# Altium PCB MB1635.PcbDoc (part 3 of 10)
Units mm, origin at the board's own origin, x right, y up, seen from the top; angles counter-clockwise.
Board outline 127 x 97 mm, 6 copper layers (Top Layer, Signal Layer 1, Signal Layer 2, Signal Layer 3, Signal Layer 4, Bottom Layer), stack 1.557 mm thick; 593 components, 478 nets, 2435 pads, 1743 vias.
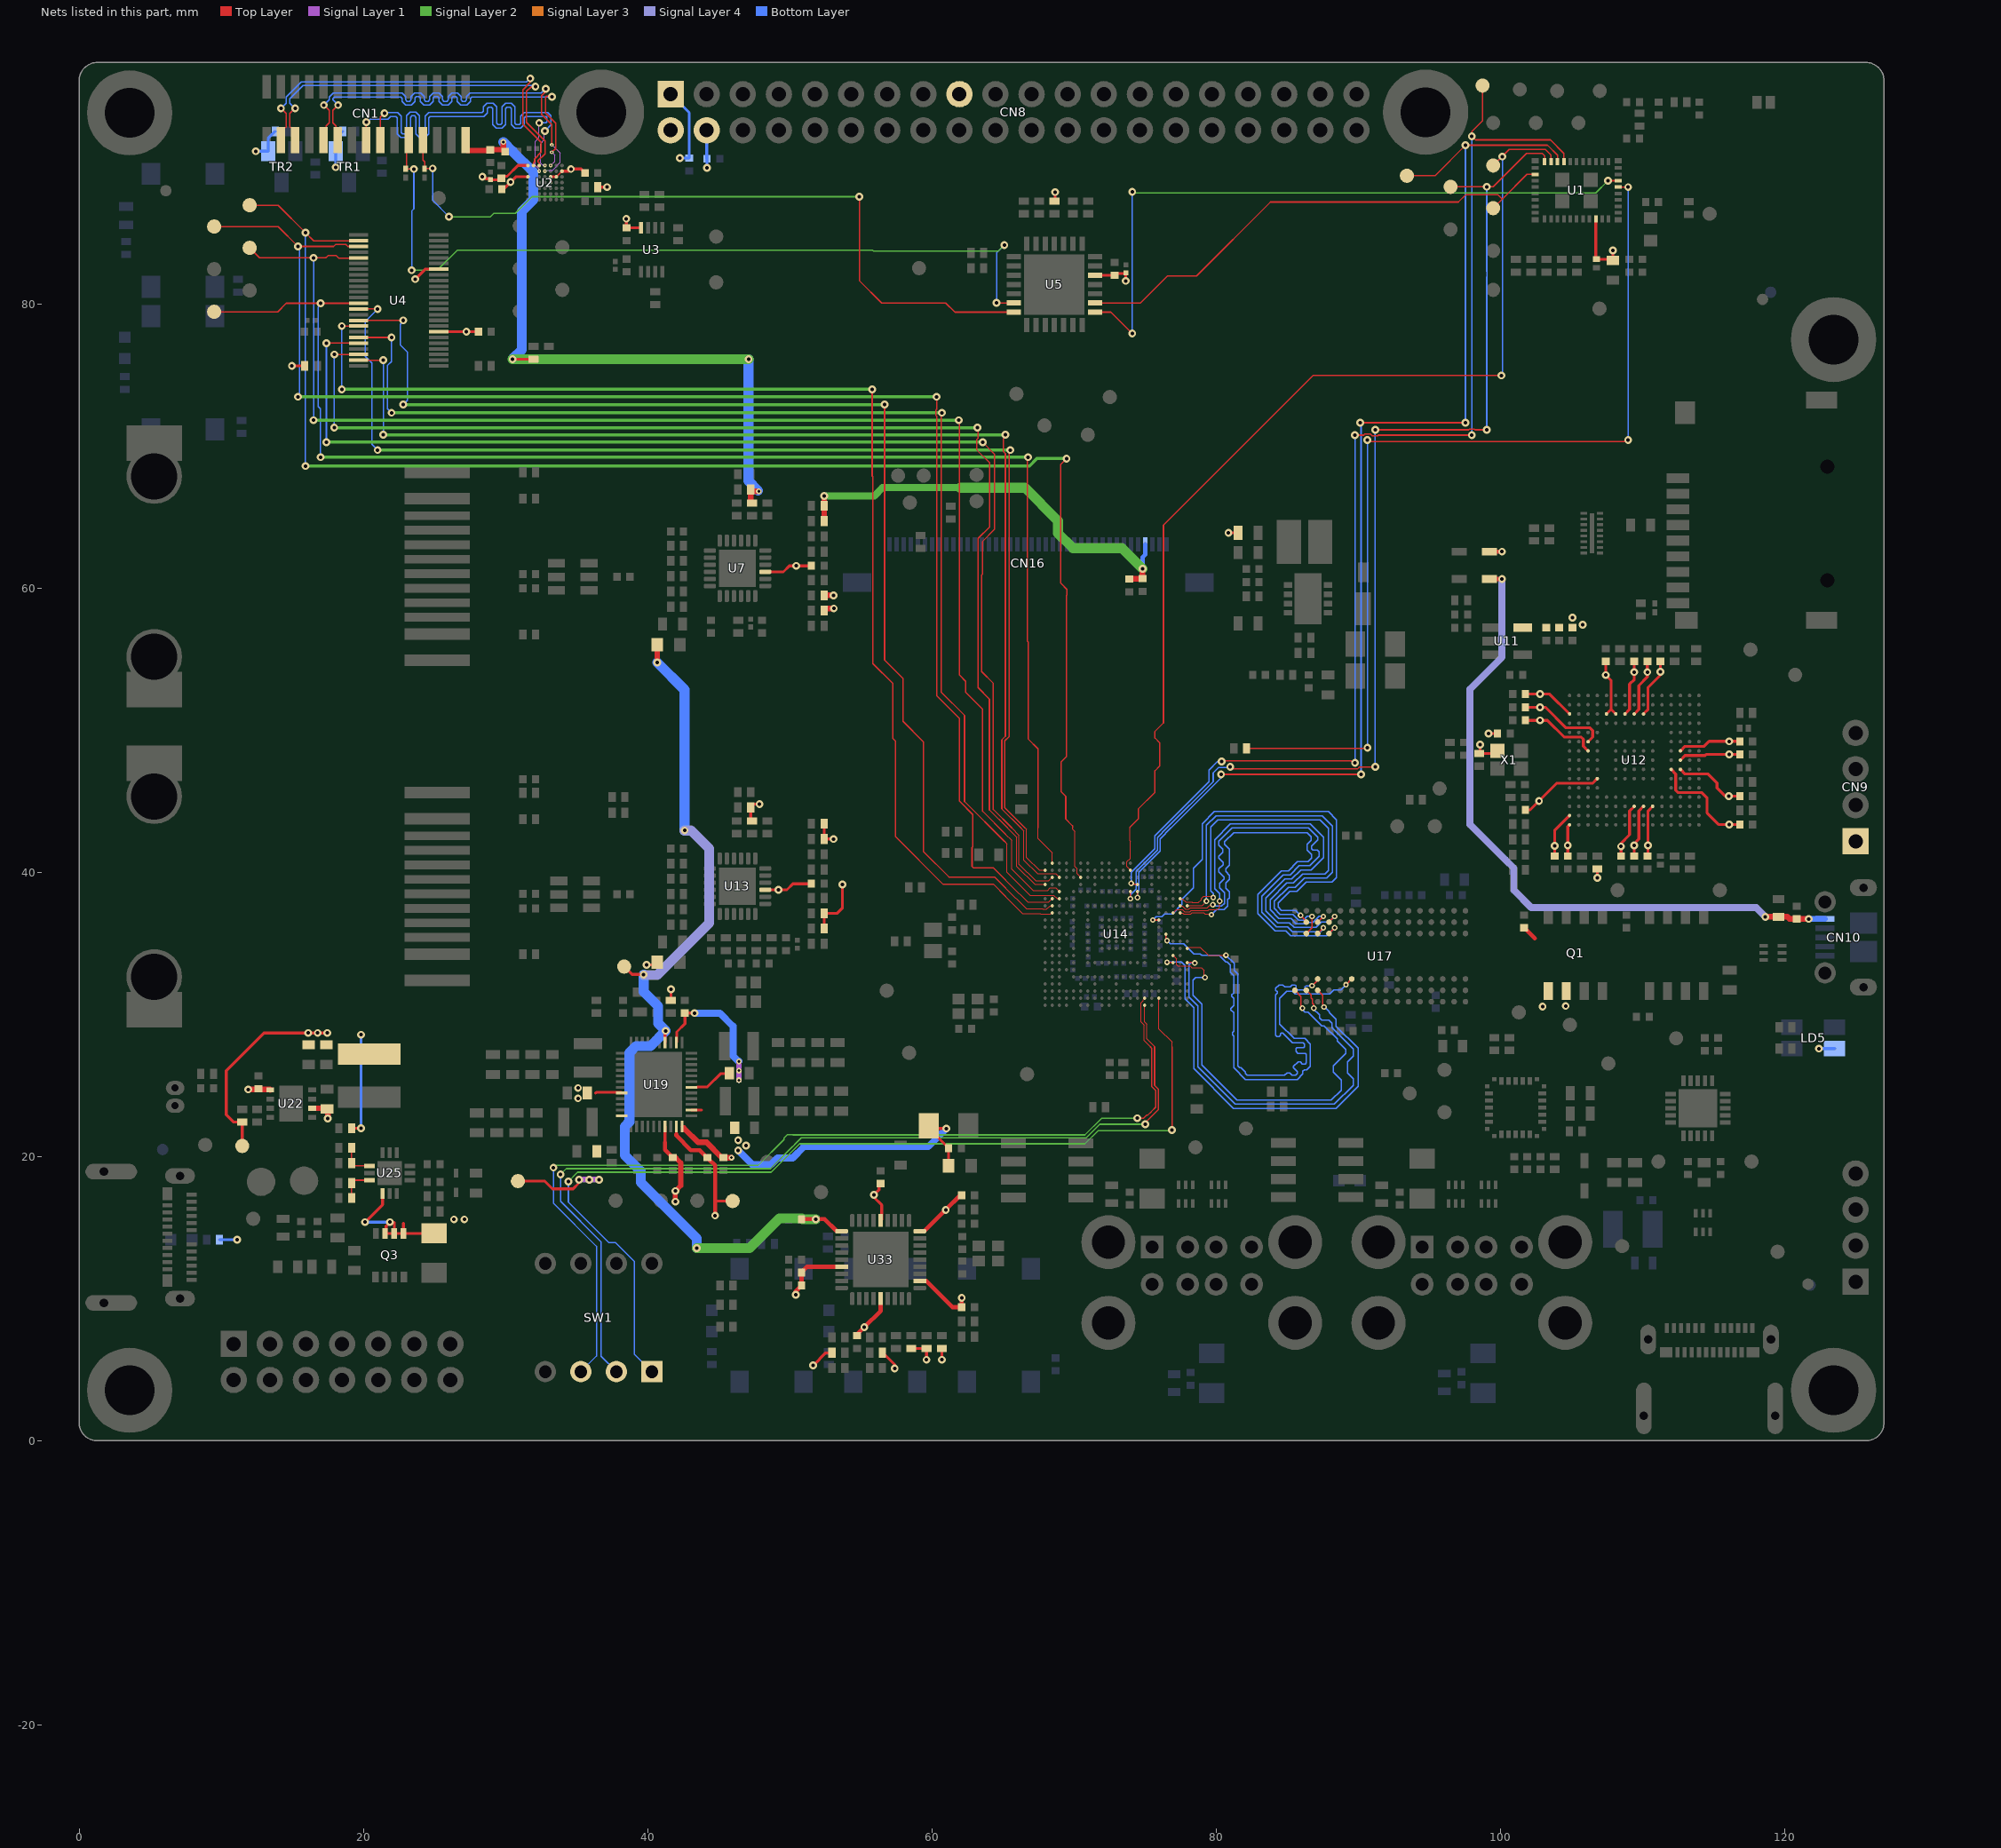
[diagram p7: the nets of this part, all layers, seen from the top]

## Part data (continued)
R31 R71 R75 R80 R82 R108 R120 R121 R168 R169: library part MCD-00068, "Resistor, 1K5, 0402, +/-1%, 1/16W", Manufacturer=YAGEO, Manufacturer_Part_Number=RC0402FR-071K5L, Package=0402
R35 R123 R127 R131 R138 R151: library part MCD-00181, "Resistor, 0R, 0603, +/- 0.5mR, 1/4W", Manufacturer=ROHM, Manufacturer_Part_Number=PMR03EZPJ000, Package=0603
R36 R41 R51 R79 R86 R98 R109: library part MCD-00455, "Resistor, 33R, 0402, +/-1%, 1/16W", Manufacturer=YAGEO, Manufacturer_Part_Number=RC0402FR-0733RL, Package=0402
R37 R39 R40 R42 R92 R95 R97 R99: library part MCD-00565, "Resistor, 49R9, 0402, +/-1%, 1/16W", Manufacturer=YAGEO, Manufacturer_Part_Number=RC0402FR-0749R9L, Package=0402
R44 R46 R156 R158 R159 R160 R161 R164 R165: library part MCD-00059, "Resistor, 100K, 0402, +/-1%, 1/16W", Manufacturer=YAGEO, Manufacturer_Part_Number=RC0402FR-07100KL, Package=0402
R47 R101: library part MCD-00723, "Resistor, 12K1, 0402, +/-1%, 1/16W", Manufacturer=YAGEO, Manufacturer_Part_Number=RC0402FR-0712K1L, Package=0402
R49: library part MCD-00060, "Resistor, 10R, 0603, +/-1%, 1/4W", Manufacturer=ROHM, Manufacturer_Part_Number=ESR03EZPF10R0, Package=0603
R50 R107: library part MCD-00189, "Resistor, 22R, 0402, +/-1%, 1/16W", Manufacturer=YAGEO, Manufacturer_Part_Number=RC0402FR-0722RL, Package=0402
R62 R63 R148: library part MCD-00433, "Resistor, 2K4, 0402, +/-1%, 1/16W", Manufacturer=YAGEO, Manufacturer_Part_Number=RC0402FR-072K4L, Package=0402
R66 R128: library part MCD-00185, "Resistor, 3K, 0402, +/-1%, 1/16W", Manufacturer=YAGEO, Manufacturer_Part_Number=RC0402FR-073KL, Package=0402
R74 R173 R175 R177 R182: library part MCD-00067, "Resistor, 100R, 0402, +/- 1%, 1/16W", Manufacturer=YAGEO, Manufacturer_Part_Number=RC0402FR-07100RL, Package=0402
R111: library part MCD-03129, "Resistor, 12mR, 0603, 1%, 1/2W", Manufacturer=PANASONIC, Manufacturer_Part_Number=ERJ-3BWFR022V, Package=0603
R112 R179: library part MCD-00120, "Resistor, 240R, 0402, +/-1%, 1/16W", Manufacturer=YAGEO, Manufacturer_Part_Number=RC0402FR-07240RL, Package=0402
R113 R124 R137: library part MCD-02234, "Resistor, 100mR, 0603, +/- 1%, 1/3W", Manufacturer=PANASONIC, Manufacturer_Part_Number=ERJ-3BWFR100V, Package=0603
R117 R125 R152 R183: library part MCD-00062, "Resistor, 330R, 0402, +/-1%, 1/16W", Manufacturer=YAGEO, Manufacturer_Part_Number=RC0402FR-07330RL, Package=0402
R126 R132: library part MCD-02233, "Resistor, 50mR, 0603, +/-1%, 1/3W", Manufacturer=PANASONIC, Manufacturer_Part_Number=ERJ-3BWFR050V, Package=0603
R129: library part MCD-00384, "Resistor, 13K, 0603,+/-1%, 1/10W", Manufacturer=YAGEO, Manufacturer_Part_Number=RC0603FR-0713KL, Package=0603
R134: library part MCD-00420, "Resistor, 2K ,0603, +/-1%, 1/10W", Manufacturer=YAGEO, Manufacturer_Part_Number=RC0603FR-072KL, Package=0603
R135: library part MCD-00521, "Resistor, 75K, 0402, +/-1%, 1/16W", Manufacturer=YAGEO, Manufacturer_Part_Number=RC0402FR-0775KL, Package=0402
R136: library part MCD-00435, "Resistor, 24K, 0402, +/-1%, 1/16W", Manufacturer=YAGEO, Manufacturer_Part_Number=RC0402FR-0724KL, Package=0402
R142: library part MCD-00259, "Resistor, 33K, 0603, +/-1%, 1/10W", Manufacturer=YAGEO, Manufacturer_Part_Number=RC0603FR-0733KL, Package=0603
R143: library part MCD-00530, "Resistor, 8K2, 0603, +/-1%, 1/10W", Manufacturer=YAGEO, Manufacturer_Part_Number=RC0603FR-078K2L, Package=0603
R145 R147: library part MCD-00333, "Resistor, 5K1, 0402, +/-1%, 1/16W", Manufacturer=YAGEO, Manufacturer_Part_Number=RC0402FR-075K1L, Package=0402
R146: library part MCD-00187, "Resistor, 12K, 0402, +/-1%, 1/16W", Manufacturer=YAGEO, Manufacturer_Part_Number=RC0402FR-0712KL, Package=0402
R153 R154 R155 R157 R170 R171 R174 R181: library part MCD-00061, "Resistor, 1K, 0402, +/-1%,1/16W", Manufacturer=YAGEO, Manufacturer_Part_Number=RC0402FR-071KL, Package=0402
R172 R184: library part MCD-00507, "Resistor, 680R, 0402, +/-1%, 1/16W", Manufacturer=YAGEO, Manufacturer_Part_Number=RC0402FR-07680RL, Package=0402
R185: library part MCD-01512, "Resistor, 1R, 0603, +/-1%, 1/10W", Manufacturer=YAGEO, Manufacturer_Part_Number=RC0603FR-071RL, Package=0603
R186: library part MCD-00489, "Resistor, 560R, 0402, +/-1%, 1/16W", Manufacturer=YAGEO, Manufacturer_Part_Number=RC0402FR-07560RL, Package=0402
SW1: library part MCD-02256, "Quad SPST switch, TH, 2.54mm pitch, height 7.5mm", Manufacturer=GRAYHILL, Package="DIP8 2.54mm pitch"
TP1 TP2 TP3 TP4 TP5 TP6 TP7 TP8 TP9 TP10 TP11 TP12 TP13 TP14 TP15 TP16 TP17 TP18 TP19 TP20 TP21 TP22 TP23 TP24 TP25 TP26 TP27 TP28 TP29 TP30 TP31 TP32 TP33 TP34 TP35 TP36 TP37 TP38 TP39 TP40 TP41 TP42 TP43 TP44 TP45 TP46 TP47 TP48 TP49 TP50 TP51 TP52 TP53 TP54 TP55 TP56 TP57 TP58 TP59 TP61 TP62 TP63 TP64 TP65 TP66 TP67 TP69 TP70 TP71 TP72 TP73 TP74 TP75 TP77: library part MCD-00074, "Test Point 1mm", Manufacturer=N/A
TP68 TP76: library part MCD-00177, "Test Point 2mm", Manufacturer=N/A
TR1 TR2: library part MCD-02156, "MOSFET, N-Channel , Vds: 25V, Id: 0,22A, Vgs(th): 1.06V, Vgs(max): +/-8V, Rdson:5ohm@Vgs=2.7V, Qg=0,49nC", Manufacturer="ON SEMICONDUCTOR", Manufacturer_Part_Number=FDV301N, Package=SOT23-3
U1: library part MCD-00268, "IEEE802.11b/g/n W-LAN + Bluetooth 4.1+EDR module", Manufacturer=MURATA, Manufacturer_Part_Number=LBEE5KL1DX-977
U2: library part MCD-02213, "Dual mode MIPI CSI-2 / SMIA CCP2 de-serializer", Manufacturer=STMICROELECTRONICS, Manufacturer_HQ_COO=EU, Manufacturer_Part_Number=STMIPID02/TR, Package="VFBGA 49-ball, 3x3x1mm, 0.4mm pitch"
U3: library part MCD-00264, "Dual bit dual supply bus transceiver", Manufacturer="TEXAS INSTRUMENTS"
U4: library part MCD-02226, "16-bit translating transceiver", Manufacturer="TEXAS INSTRUMENTS", Manufacturer_Part_Number=SN74AVC16T245DGVR, Package="TVSOP,  56-ball 4.5x7mm, 0.65mm pitch"
U5: library part MCD-02210, "16-bit port expander with I2C control", Manufacturer=MICROCHIP, Manufacturer_Part_Number=MCP23017T-E/ML, Package="QFN28 6x6mm"
U6: library part MCD-00249, "ESD protection for SD card 2.0", Manufacturer=STMICROELECTRONICS, Manufacturer_HQ_COO=EU
U7 U13: library part MCD-00719, "10/100M RMII Ethernet transceiver", Manufacturer=MICROCHIP
U8 U15: library part MCD-00250, "Very low capacitance ESD protection , 4 lines", Manufacturer=STMICROELECTRONICS, Manufacturer_HQ_COO=EU
U9: library part MCD-00082, "White LED power supply for large display backlight, QFN8", Manufacturer=STMICROELECTRONICS, Manufacturer_HQ_COO=EU
U10 U37 U40 U41: library part MCD-00170, "ESD protection 6V1", Manufacturer=STMICROELECTRONICS, Manufacturer_HQ_COO=EU, Manufacturer_Part_Number=ESDALC6V1-1U2
U11: library part MCD-00086, "Ultra low drop-low noise BiCMOS voltage, regulators low ESR capacitors compatible", Manufacturer=STMICROELECTRONICS, Manufacturer_HQ_COO=EU
U12: library part MCD-01523, "MCU, Arm Cortex-M7 32-bit MCU, 512KB Flash, 276KB RAM, With Crypto", Manufacturer=STMICROELECTRONICS, Manufacturer_HQ_COO=EU, Manufacturer_Part_Number=STM32F723IEK6, Package=ICC_UFBGA201_176+25_10X10_P065
U14: library part MCD-02251, "Cortex-A7 @ 900MHz, 128KB-ROM, 128KB-SRAM, 2x Ethernet, 2x ADC, 2x CAN FD, TSC, Camera, Display, Secure Boot, Cryptography, DRAM enc/dec, PKA", Manufacturer=STMICROELECTRONICS, Manufacturer_HQ_COO=EU, Package=TFBGA320
U16: library part MCD-00251, "High power transient voltage suppressor, 7V breakdown", Manufacturer=STMICROELECTRONICS, Manufacturer_HQ_COO=EU, Manufacturer_Part_Number=ESDA7P60-1U1M
U17: library part MCD-01811, "Memory,DDR3L,4Gb,256Mbx16,933Mhz,1V35,TFBGA", Manufacturer=NANYA
U18 U26 U27 U28 U29 U32: library part MCD-00649, "Common mode filter with ESD protection for USB 2.0 interface", Manufacturer=STMICROELECTRONICS, Manufacturer_HQ_COO=EU
U19: library part MCD-02275, "ST PMIC: 4 step-down +1 advanced boost SMPS, 6 LDOs, 2 pwr switches, DDR Vref, NVM option 'D' for IO@3.3V", Manufacturer=STMICROELECTRONICS, Manufacturer_Part_Number=STPMIC1DPQR, Package="WFQFN 5.0x6.0x0.80mm"
U20: library part MCD-02130, "USB Type-C Port Protection for USB DRP Power Delivery, PPS compliant", Manufacturer=STMICROELECTRONICS, Manufacturer_HQ_COO=EU, Package=QFN-20L
U21: library part MCD-02218, "Arm Cortex-M0+ 32-bit MCU, up to 128 KB Flash, 36 KB RAM,  4x USART, timers, ADC, DAC, comm. I/Fs, 1.7-3.6V", Manufacturer=STMICROELECTRONICS, Manufacturer_HQ_COO=EU, Package=UFQFPN28
U22: library part MCD-02243, "3A DC step-down switching regulator 1,5MHz", Manufacturer=STMICROELECTRONICS, Manufacturer_HQ_COO=EU, Package="VFDFPN 3x3mm - 8L"
U23 U24: library part MCD-00123, "IC,Dual-Channel-Power-Switch,500mA,100mR,SO8", Manufacturer=STMICROELECTRONICS, Manufacturer_HQ_COO=EU
U25: library part MCD-01809, "USB Type-C Port Protection for USB Power Delivery, PPS compliant", Manufacturer=STMICROELECTRONICS, Manufacturer_HQ_COO=EU, Package=QFN-12L
U30 U31 U38 U39: library part MCD-01026, "High power transient voltage suppressor", Manufacturer=STMICROELECTRONICS, Manufacturer_HQ_COO=EU, Manufacturer_Part_Number=ESDA7P120-1U1M, Package=QFN1610
U33: library part MCD-00145, "USB HUB 2,0 Controller", Manufacturer=MICROCHIP
U34 U36: library part MCD-01207, "High power Transient voltage suppressor:25V/35A EOS and ESD transients protection.", Manufacturer=STMICROELECTRONICS, Manufacturer_HQ_COO=EU, Manufacturer_Part_Number=ESDA25P35-1U1M, Package=QFN1610
U35: library part MCD-02422, "LCD,  TFT, 4.3 inch, 480x272 pixels with LED Backlight and Capacitive touch panel, high luminance with 0.5mm pitch flat cable", Manufacturer=ROCKTECH, Manufacturer_Part_Number=RK043FN78HV-CT661C
X1: library part MCD-00597, "Oscillator, SPXO, 25Mhz, +/-50ppm, 3V3, square wave, 2.5x2mm", Manufacturer=NDK, Manufacturer_Part_Number=NZ2520SH-25MHZ-END4869C, Package=2.5x2mm
X2: library part MCD-01479, "Crystal, 32.768kHz, 6pF, +/-20ppm, 80K, 2.05x1.2mm", Manufacturer=NDK, Manufacturer_Part_Number=NX2012SA-32.768KHZ-EXS00A-MU00527, Package=2.05x1.2mm
X3: library part MCD-01364, "Crystal, 25MHz, 6pF, +/-20ppm, 80R, 2x1.6mm", Manufacturer=NDK, Manufacturer_Part_Number=NX2016SA-25MHZ-EXS00A-CS11321, Package=2x1.6mm
X4 X5: library part MCD-01036, "Crystal, 24MHz, 6pF, +/-20ppm, 80R, 2x1.6mm", Manufacturer=NDK, Manufacturer_Part_Number=NX2016SA-24MHZ-EXS00A-CS10820, Package=2x1.6mm

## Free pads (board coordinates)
  round 6 hole 3.5: 1(3.55,3.55) 1(3.55,93.45) 1(36.75,93.5) 1(94.75,93.5) 1(123.45,3.55) 1(123.45,77.5)

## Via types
v1: diameter 0.55, hole 0.25, Top Layer to Bottom Layer, 1438 vias
v2: diameter 0.4, hole 0.2, Top Layer to Bottom Layer, 276 vias
v3: diameter 0.26, hole 0.1, Top Layer to Signal Layer 1, tented both sides, 29 vias

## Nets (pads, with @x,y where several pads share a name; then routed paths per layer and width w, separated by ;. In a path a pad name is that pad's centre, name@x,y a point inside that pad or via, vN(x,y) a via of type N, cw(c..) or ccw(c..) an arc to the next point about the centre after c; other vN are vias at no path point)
1V8_PERIPH: C9.2 C10.2 C11.2 C12.2 C13.2 C26.2 C145.2 R5.1 R22.2 R168.2 R169.2 TP72.1 TR1.1 TR2.1 U2.A2 U2.B3 U2.C3 U2.C4 U2.G1 U2.G3 U3.8 U4.31 U4.42 U19.21 | length 31.2
  Top Layer w0.1: U2.B3@33.575,88.95 U2.A2@33.975,89.35
  Top Layer w0.2: v1(14.975,75.65) R22.2@15.875,75.65 ; v1(23.65,81.75) 24.35,82.45 U4.42@25.3,82.45 ; U4.31@25.3,78.05 C26.2@28.1,78.05 ; v1(28.375,88.95) 28.47,88.95 28.6,88.82 28.875,88.82 C10.2@28.95,88.745 29.595,88.745 C9.2@29.7,88.85 ; C9.2@29.7,88.95 29.742,88.992 30.117,88.992 30.875,89.75 U2.G1@31.575,89.75 ; C12.2@29.75,88.075 29.85,88.075 30.725,88.95 U2.G3@31.575,88.95 ; U2.C4@33.175,88.55 U2.C3@33.175,88.95 U2.B3@33.575,88.95 ; U2.A2@33.975,89.35 34.45,89.35 v1(34.6,89.5) 35.325,89.5 C11.2@35.6,89.225 ; R5.1@36.5,88.225 v1(37.15,88.225) ; v1(38.5,86) 38.5,85.38 C13.2@38.515,85.365 U3.8@39.54,85.365 ; 42.025,21.55 U19.21@42.025,22.125 ; 44.75,16.875 TP72.1@45.987,16.875
  Top Layer w0.3: 42.025,21.55 42.025,21.475 43.05,20.45 43.675,20.45 44.07,20.055 44.07,20.03 44.175,19.925 C145.2@44.2,19.925 ; C145.2@44.225,19.925 44.33,19.82 44.33,19.795 44.75,19.375 44.75,17.794 44.75,17.625 44.75,16.875 v1(44.75,15.85)
  Bottom Layer w0.2: v1(12.425,90.75) TR2.1@13.3,90.75 13.3,91.65 R169.2@13.8,92.15 ; v1(18.05,89.625) TR1.1@18.05,90.75 18.05,91.65 R168.2@18.55,92.15
  other v1: 27.25,78.05 30.35,88.575
3V3_AO: C7.1 C18.2 C19.2 C22.2 C23.2 C79.2 C113.2 C114.2 CN8.1 CN8.17 L5.2 L8.2 R9.1 R73.2 R78.2 R80.2 R83.2 R100.2 R102.2 R115.1 R135.2 R186.2 TP62.1 U1.30 U5.5 U13.9 | length 48.1
  Top Layer w0.2: TP62.1@11.475,20.75 R135.2@11.475,22.425 10.875,22.425 10.35,22.95 10.35,26.05 13,28.7 v1(16.125,28.7) v1(16.788,28.7) v1(17.45,28.7) ; R186.2@19.175,22 v1(19.825,22) ; v1(39.925,33.5) 40.5,33.5 L5.2@40.675,33.675 ; R115.1@41.625,31 41.652,31.027 41.65,31.029 41.652,31.031 v1(41.652,31.777) ; R78.2@47.35,43.625 47.25,43.725 R73.2@47.25,44.575 47.475,44.8 v1(47.875,44.8) ; U13.9@48.275,38.775 49.8,38.775 50.225,39.2 C79.2@51.525,39.2 ; R102.2@52.425,36.05 R100.2@52.425,37.125 53.35,37.125 53.7,37.475 v1(53.7,39.15) ; R80.2@52.425,43.425 R83.2@52.425,42.35 v1(53.075,42.35) ; R9.1@68.625,87.25 68.675,87.3 v1(68.675,87.875) ; U5.5@71.475,82.025 C22.2@72.85,82.025 72.975,82.15 73.6,82.15 C23.2@73.65,82.2 v1(73.65,81.625) ; U1.30@106.725,85.975 106.725,83.2 C18.2@106.775,83.15 107.85,83.15 C19.2@107.925,83.075 v1(107.925,83.775)
  Bottom Layer w0.2: v1(19.825,22) v1(19.825,28.575) ; CN8.1@41.62,94.77 42.925,93.465 C7.1@42.925,90.275 v1(42.275,90.275)
  other v1: 49.2,38.775
3V3_STLK: C42.2 C43.2 C44.2 C46.2 C47.2 C48.2 C49.2 C57.2 C58.2 C59.2 C61.2 C62.2 C63.2 C67.2 C68.2 C69.2 C74.2 C75.2 C76.2 C77.2 C78.2 CN9.1 LD5.3 R65.1 R89.1 U11.5 U12.C1 U12.C5 U12.C6 U12.C7 U12.C8 U12.C9 U12.F3 U12.G3 U12.G13 U12.H13 U12.J12 U12.J13 U12.K4 U12.N8 U12.N9 U12.N10 U12.P1 U12.R1 X1.4 | length 81.1
  Top Layer w0.2: v1(98.575,49) 98.575,48.425 R65.1@98.525,48.375 99.625,48.375 X1.4@99.8,48.55 ; v1(99.175,49.775) C61.2@99.8,49.775 ; C68.2@101.775,44.4 102.1,44.4 v1(102.725,45.025) 103.975,46.275 106.5,46.275 U12.K4@106.825,46.6 ; C59.2@101.775,50.7 v1(102.8,50.7) 103.325,50.7 104.5,49.525 105.7,49.525 105.85,49.375 105.85,48.875 U12.G3@106.175,48.55 ; C58.2@101.775,51.625 v1(102.8,51.625) 103.175,51.625 104.625,50.175 106.31,50.175 106.5,49.985 106.5,49.525 U12.F3@106.175,49.2 ; C57.2@101.775,52.55 v1(102.8,52.55) 103.475,52.55 U12.C1@104.875,51.15 ; C74.2@103.825,41.15 v1(103.825,41.875) 103.825,42.95 U12.P1@104.875,44 ; C75.2@104.75,41.15 v1(104.75,41.9) 104.75,43.225 U12.R1@104.875,43.35 ; v1(106.825,39.625) R89.1@106.825,40.25 ; C46.2@107.425,54.85 v1(107.425,53.889) 107.8,53.514 107.8,51.475 ; U12.C5@107.475,51.15 107.8,51.475 ; U12.C6@108.125,51.15 107.8,51.475 ; C76.2@108.5,41.15 v1(108.5,41.825) 108.5,42.05 109.1,42.65 109.1,44.325 U12.N8@109.425,44.65 ; U12.C7@108.775,51.15 109.1,51.475 109.1,53.25 109.425,53.575 v1(109.425,54.1) C47.2@109.425,54.85 ; C77.2@109.425,41.15 v1(109.425,41.9) 109.425,42.025 109.75,42.35 109.75,44.325 U12.N9@110.075,44.65 ; U12.C8@109.425,51.15 109.75,51.475 109.75,53.15 110.35,53.75 v1(110.35,54.1) C48.2@110.35,54.85 ; U12.C9@110.075,51.15 110.4,51.475 110.4,53.025 111.275,53.9 C49.2@111.275,54.85 ; C78.2@110.35,41.15 110.4,41.2 v1(110.4,41.9) 110.4,44.325 U12.N10@110.725,44.65 ; U12.J12@112.025,47.25 112.35,46.925 112.35,45.775 112.5,45.625 114.15,45.625 114.55,45.225 114.55,44.175 115.35,43.375 v1(116.1,43.375) C69.2@116.85,43.375 ; U12.J13@112.675,47.25 113,46.925 114.625,46.925 115.25,46.3 115.25,45.95 115.825,45.375 v1(116.075,45.375) C67.2@116.85,45.375 ; U12.H13@112.675,47.9 113,48.225 114.4,48.225 114.475,48.3 v1(116.1,48.3) C63.2@116.85,48.3 ; U12.G13@112.675,48.55 113,48.875 114.35,48.875 114.7,49.225 v1(116.1,49.225) C62.2@116.85,49.225
  Bottom Layer w0.2: v1(122.425,27.6) LD5.3@123.525,27.6
  other v1: 111.275,54.125 105.8,57.425 105.075,57.925
3V3_SW: C6.2 C30.2 C50.1 C53.2 C117.2 C150.2 C154.2 C157.2 C165.2 C168.2 C169.2 C170.2 CN1.15 CN16.4 L4.2 R20.2 R26.2 R29.2 R31.2 R32.2 R43.2 R48.2 R161.2 R162.1 R163.2 R164.2 R165.2 TP49.1 U7.9 U19.38 U33.5 U33.10 U33.15 U33.23 U33.29 U33.36 | length 177
  Top Layer w0.2: v1(30.5,76.125) R20.2@31.975,76.125 ; TP49.1@38.35,33.375 38.9,32.825 39.699,32.825 v1(39.719,32.805) ; U19.38@41.225,28.025 41.225,28.384 41.225,28.799 v1(41.277,28.851) ; U7.9@48.275,61.15 49.55,61.15 49.975,61.575 v1(50.45,61.575) C30.2@51.525,61.575 ; v1(51.65,5.3) 52.537,6.187 52.962,6.187 R164.2@52.975,6.2 ; U33.5@56.4,15.5 56.475,15.575 56.475,16.597 55.925,17.147 v1(55.925,17.3) 56.287,17.662 56.287,17.987 C150.2@56.4,18.1 ; R165.2@56.525,6.2 56.55,6.2 57.382,5.368 v1(57.382,5.089) ; R161.2@58.55,6.5 R162.1@59.625,6.5 v1(59.625,5.7) ; v1(60.7,5.7) R163.2@60.7,6.5
  Top Layer w0.3: v1(50.425,10.275) 50.425,10.525 C168.2@50.825,10.925 C165.2@50.825,11.85 51.225,12.25 U33.15@53.65,12.25 ; C157.2@50.825,15.6 52.45,15.6 53.3,14.75 U33.10@53.65,14.75 ; C170.2@54.75,7.4 54.75,7.5 v1(55.25,8) 56.4,9.15 U33.23@56.4,10 ; U33.29@59.15,11.25 59.611,11.25 61.461,9.4 C169.2@62.1,9.4 v1(62.1,10.05) ; U33.36@59.15,14.75 59.475,14.75 v1(60.975,16.25) ; v1@61.075,16.25 v1(60.975,16.25) ; C154.2@62.1,17.275 62,17.275 v1(60.975,16.25)
  Top Layer w0.4: CN1.15@27.2,91.525 27.2,90.905 27.3,90.805 27.985,90.805 28.265,90.805 28.88,90.805 28.907,90.832 C117.2@28.925,90.85 28.939,90.864 29.805,90.864 29.864,90.805 29.92,90.805 29.975,90.75 C6.2@29.975,90.725 ; C6.2@29.85,90.95 v2(29.85,91.4) ; v1(40.675,54.775) L4.2@40.675,56.025 ; R29.2@47.35,66 47.25,66.1 R26.2@47.25,66.95 47.375,66.825 v2(47.825,66.825) ; R48.2@52.425,58.425 52.575,58.575 v1(53.1,58.575) ; R43.2@52.425,59.5 v1(53.075,59.5) ; R32.2@52.425,64.725 R31.2@52.425,65.8 v1(52.425,66.5) ; C50.1@73.905,60.675 74.83,60.675 74.825,60.68 v1(74.825,61.374)
  Signal Layer 2 w0.5: v1(30.5,76.125) v1@30.503,76.125 ; v1(52.425,66.5) 55.95,66.5 56.525,67.075 62,67.075
  Signal Layer 2 w0.7: v1@30.503,76.125 v1(47.1,76.125) ; v1(43.45,13.55) 47.175,13.55 49.275,15.65 50.85,15.65 50.903,15.598 v1(51.835,15.598) ; 62,67.075 66.55,67.075 68.875,64.75 68.875,63.875 69.925,62.825 73.374,62.825 v1(74.825,61.374)
  Signal Layer 4 w0.7: v1@39.749,32.775 40.675,32.775 44.325,36.425 44.325,41.675 43.05,42.95 v1(42.6,42.95)
  Bottom Layer w0.3: v1(74.825,61.374) 74.825,62.171 75.025,62.371 CN16.4@75.025,63.1
  Bottom Layer w0.7: v2(29.85,91.4) 30.5,90.75 31.95,89.3 31.95,87.325 31.15,86.525 31.15,76.775 v1@30.536,76.161 ; v1(39.719,32.805) 39.719,31.606 40.742,30.583 40.742,29.386 v1(41.277,28.851) 40.201,27.775 39.185,27.775 38.725,27.315 38.725,22.45 38.4,22.125 38.4,20.1 39.525,18.975 39.525,18.175 43.45,14.25 v1(43.45,13.55) ; v1(40.675,54.775) 42.6,52.85 v1(42.6,42.95) ; v1(47.1,76.125) 47.1,67.55 v2@47.779,66.871
5V_USB_CHGR: C84.2 CN10.1 D3.1 U16.1 | length 47.7
  Top Layer w0.3: D3.1@99.245,60.65 v1(100.125,60.65)
  Top Layer w0.4: v1(118.65,36.875) U16.1@119.575,36.875 120.2,36.875 120.35,36.725 C84.2@120.85,36.725 v1(121.7,36.725)
  Signal Layer 4 w0.5: v1(100.125,60.65) 100.125,55.15 97.875,52.9 97.875,43.375 100.366,40.884 100.965,40.285 100.965,38.735 102.175,37.525 118,37.525 v1(118.65,36.875)
  Bottom Layer w0.4: v1(121.7,36.725) CN10.1@122.85,36.725
5V_VIN: C8.2 C86.2 C101.2 C120.2 C122.2 C123.2 C125.2 C130.2 C131.2 C134.2 C135.2 C143.2 C146.2 C162.1 CN8.2 CN8.4 D1.1 L12.1 Q1.5 Q1.6 Q3.1 Q3.2 Q3.3 R35.1 R152.2 TP67.1 U19.8 U19.12 U19.19 U19.22 U19.24 U19.28 U19.36 U22.1 U22.6 U25.4 | length 79.5
  Top Layer w0.2: v1(20.12,15.389) 21.345,16.614 U25.4@21.345,17.414 ; v1(21.87,15.389) 21.594,15.114 21.594,14.664 Q3.3@21.52,14.589 Q3.2@22.17,14.589 ; 22.17,15.364 Q3.2@22.17,14.589 ; 22.82,15.314 Q3.1@22.82,14.589 ; C162.1@24.97,14.614 24.945,14.589 Q3.1@22.82,14.589 ; TP67.1@30.875,18.275 32.75,18.275 33.3,17.725 34.75,17.725 35.175,18.15 v1(35.175,18.375) ; 36.34,24.475 36.391,24.526 38.124,24.526 U19.8@38.175,24.475 ; 41.225,21 U19.19@41.225,22.125 ; U19.36@42.025,28.025 42.052,28.052 42.052,28.777 42.625,29.35 C101.2@42.625,30.1 v1(43.3,30.1) ; 42.6,21.95 U19.22@42.425,22.125 42.609,22.125 ; U19.24@43.075,23.275 43.8,23.275 ; U19.28@43.075,24.875 43.48,24.875 43.506,24.901 44.204,24.901 45.15,25.847 45.747,25.847 C120.2@45.75,25.85 ; v1(61.025,21.975) 59.975,21.975 C130.2@59.775,22.175 59.775,22 C135.2@61.175,20.6 L12.1@61.175,19.35 ; v1(80.875,63.9) R35.1@81.55,63.9 ; Q3.2@22.17,14.589 Q3.1@22.82,14.589
  Top Layer w0.3: 41.225,21 41.225,20.475 C143.2@41.775,19.925 ; 42.6,21.85 42.6,21.95 ; D1.1@99.245,62.575 v1(100.125,62.575) ; C86.2@101.675,36.1 102.425,35.35
  Top Layer w0.35: v1(41.95,16.825) v1(41.95,17.575) 42.335,17.96 42.335,19.56 C143.2@41.97,19.925
  Top Layer w0.4: v1(11.9,24.725) 13.425,24.725 U22.1@13.45,24.7 ; U22.6@16.4,23.4 17.4,23.4 C123.2@17.45,23.35 17.525,23.275 17.5,23.25 v1(17.5,22.675) ; C143.2@41.775,19.925 C143.2@41.97,19.925 ; 42.6,21.95 43.55,21 44.15,21 C146.2@45.161,19.989 ; C146.2@45.25,19.925 v2(45.9,19.925)
  Signal Layer 1 w0.4: v1(35.175,18.375) v1(35.9,18.375) v1(36.575,18.375) ; v2(46.425,25.375) v2(46.425,26.05) v2(46.425,26.7)
  Signal Layer 2 w0.4: v2(46.425,25.375) v2(46.425,26.05) v2(46.425,26.7)
  Signal Layer 3 w0.4: v2(46.425,25.375) v2(46.425,26.05) v2(46.425,26.7)
  Signal Layer 4 w0.4: v2(46.425,25.375) v2(46.425,26.05) v2(46.425,26.7)
  Bottom Layer w0.2: R152.2@9.875,14.15 v1(11.125,14.15) ; v1(20.12,15.389) v1(21.87,15.389) ; CN8.4@44.16,92.23 44.16,90.24 C8.2@44.175,90.225 v1(44.175,89.575)
  Bottom Layer w0.4: v2(46.425,25.375) v2(46.425,26.05) v2(46.425,26.7)
  Bottom Layer w0.5: v1(43.3,30.1) 45.075,30.1 46.007,29.168 46.007,27.093 ; 46.007,27.732 46.007,27.093 ; v1(46.375,20.425) 47.375,19.425 48.675,19.425 49.15,19.9 50.2,19.9 51,20.7 59.75,20.7 v1(61.025,21.975) ; v2(46.425,26.7) 46.4,26.7 46.007,27.093
  other v1: 26.375,15.575 27.1,15.575 46.925,20.775 46.375,21.15 35.1,24.1 35.1,24.825 102.975,30.55 104.6,30.6
BOOT0: SW1.1 U14.Y17 | length 69.7
  Top Layer w0.075: U14.Y17@75.974,31.15 75.974,28.988 76.9,28.062 76.9,27.725
  Top Layer w0.1: v1(76.9,21.875) 76.9,27.725
  Signal Layer 2 w0.1: v1(34.425,18.25) 35.076,18.901 41.928,18.901 48.685,18.901 50.684,20.9 70.775,20.9 71.7,21.825 76.85,21.825 v1(76.9,21.875)
  Bottom Layer w0.1: v1(34.425,18.25) 34.425,16.8 37.286,13.939 37.761,13.939 39.075,12.625 39.075,6.09 SW1.1@40.3,4.865
BOOT1: SW1.2 U14.AA15 | length 67.3
  Top Layer w0.075: U14.AA15@74.974,30.65 74.975,29.471 75.115,29.331 75.115,28.285 75.675,27.725
  Top Layer w0.1: v1(75.025,22.275) 75.025,22.392 75.95,23.317 75.95,24.733 75.675,25.008 75.675,27.725
  Signal Layer 2 w0.1: v1(33.875,18.75) 33.877,18.75 34.277,19.15 48.65,19.15 50.2,20.7 ; 50.201,20.7 50.45,20.949 ; 50.45,20.95 50.825,21.325 70.858,21.325 71.808,22.275 v1(75.025,22.275)
  Bottom Layer w0.1: v1(33.875,18.75) 33.875,16.85 36.725,14 36.725,5.94 SW1.2@37.8,4.865
BOOT2: SW1.3 U14.Y15 | length 68.5
  Top Layer w0.075: U14.Y15@74.974,31.15 74.974,31.113 74.89,31.028 74.89,30.978 74.728,30.816 74.728,29.479 74.945,29.262 74.945,28.155 75.375,27.725
  Top Layer w0.1: v1(74.45,22.7) 74.895,22.7 75.12,22.925 75.201,22.925 75.45,23.174 ; 75.375,27.725 75.475,27.625 75.475,24.925 75.75,24.65 75.75,23.475 75.45,23.175
  Signal Layer 2 w0.1: v1(33.375,19.225) 33.525,19.375 47.776,19.375 49.6,21.199 49.6,21.301 49.849,21.55 50.201,21.55 50.226,21.525 70.775,21.525 71.95,22.7 v1(74.45,22.7)
  Bottom Layer w0.1: v1(33.375,19.225) 33.375,16.713 36.4,13.688 36.4,5.965 SW1.3@35.3,4.865
BT_DEV_WAKE: U1.39 U5.1 | length 47.8
  Top Layer w0.1: U5.1@71.475,79.425 72.6,79.425 v1(74.1,77.925) ; v1(107.575,88.675) U1.39@108.3,88.675
  Signal Layer 2 w0.1: v1(74.1,87.9) 74.175,87.825 106.725,87.825 v1(107.575,88.675)
  Bottom Layer w0.1: v1(74.1,77.925) v1(74.1,87.9)
BT_HOST_WAKE: R64.1 U1.38 | length 67.1
  Top Layer w0.1: R64.1@82.15,48.725 v1@90.65,48.725 ; v1(90.65,70.425) 90.772,70.425 90.872,70.325 108.716,70.325 108.73,70.339 108.914,70.339 v1(109,70.425) ; U1.38@108.3,88.225 v1(109,88.225)
  Bottom Layer w0.1: v1(90.65,70.425) 90.654,70.421 v1(90.654,48.777) ; v1(109,70.425) v1(109,88.225)
BT_PCM_CLK: TP11.1 U1.11 U14.E13 | length 80.3
  Top Layer w0.09: v2(73.975,38.15) U14.E13@73.975,38.65
  Top Layer w0.1: v1(81,47.425) 81.148,47.277 89.955,47.277 90.103,47.425 v1(91.2,47.425) ; v1(91.2,71.15) 97.774,71.15 97.824,71.2 98.176,71.2 98.226,71.15 v1(99.05,71.15) ; TP11.1@96.5,88.25 99.5,88.25 101.85,90.6 102.95,90.6 103.125,90.425 U1.11@103.125,90.025
  Bottom Layer w0.09: v2(73.975,38.15) 73.975,38.425 74.376,38.826 74.376,40.086 74.9,40.61 75.866,41.576 75.866,41.666 75.866,42.449 76.542,43.125
  Bottom Layer w0.1: 76.542,43.125 79.8,46.383 79.8,47 80.175,47.375 80.95,47.375 v1(81,47.425) ; v1(91.2,47.425) v1(91.2,71.15) ; v1(99.05,71.15) 99.05,81.899 99.075,81.924 99.075,82.276 99.05,82.301 v1(99.05,88.25)
BT_PCM_SDI: TP8.1 U1.10 U14.B13 | length 74.5
  Top Layer w0.075: 73.94,43.125 73.94,42.235 73.965,42.21 73.965,40.989 73.725,40.749 73.725,40.4 U14.B13@73.975,40.15
  Top Layer w0.1: 73.94,43.125 73.94,43.181 74.525,43.766 74.525,44.455 75.7,45.63 75.7,47.152 76.025,47.477 76.025,49.138 75.7,49.463 75.7,49.925 76.3,50.525 76.3,64.45 86.425,74.575 ; 86.426,74.575 86.675,74.824 ; 86.675,74.825 86.825,74.975 v1(100.075,74.975) ; TP8.1@99.5,89.75 100.625,90.875 103.175,90.875 103.575,90.475 U1.10@103.575,90.025
  Bottom Layer w0.1: v1(100.075,74.975) 100.15,75.05 v1(100.15,90.375)
BT_PCM_SDO: TP9.1 U1.9 U14.E14 | length 85.4
  Top Layer w0.09: v2@74.475,38.15 U14.E14@74.475,38.65
  Top Layer w0.1: v1(80.35,46.9) 90.075,46.9 v1@90.15,46.975 ; v1(90.15,71.65) v1(97.55,71.65) ; TP9.1@93.425,89.025 95.4,89.025 v1(97.55,91.175) 103.325,91.175 104.025,90.475 U1.9@104.025,90.025
  Bottom Layer w0.09: v2(74.475,38.225) 74.475,38.665 74.56,38.75 74.56,40.01 74.9,40.35 76.05,41.5 76.05,41.85 76.05,42.35 76.825,43.125
  Bottom Layer w0.1: 76.825,43.125 v1@80.35,46.65 ; v1@80.35,46.65 v1(80.35,46.9) ; v1(90.15,71.65) 90.204,71.596 v1(90.204,46.902) ; v1(97.55,71.65) v1(97.55,91.175)
BT_PCM_WS: TP1.1 U1.8 U14.D14 | length 85.1
  Top Layer w0.09: v2@74.075,39.15 U14.D14@74.475,39.15
  Top Layer w0.1: v1(80.4,47.8) 80.45,47.85 89.51,47.85 89.658,47.702 v1(89.779,47.702) ; v1(89.775,70.775) 90.399,70.775 90.474,70.85 90.863,70.85 90.988,70.725 91.376,70.725 91.426,70.775 v1(98,70.775) ; TP1.1@98.75,95.375 98.75,92.9 98,92.15 v1(98,91.8) 98.018,91.8 98.268,91.55 103.525,91.55 104.475,90.6 U1.8@104.475,90.025
  Bottom Layer w0.09: v2(74.025,39.225) 74.025,40 75.682,41.657 75.682,42.557 76.25,43.125
  Bottom Layer w0.1: 76.25,43.125 79.5,46.375 79.5,47.2 80.1,47.8 v1(80.4,47.8) ; v1(89.775,70.775) 89.779,70.771 v1(89.779,47.702) ; v1(98,70.775) v1(98,91.8)
BT_REG_ON: TP14.1 U1.14 U5.2 | length 35.9
  Top Layer w0.1: U5.2@71.475,80.075 74.675,80.075 76.575,81.975 78.625,81.975 83.825,87.175 97.05,87.175 97.575,87.7 99.825,87.7 100.138,87.388 ; TP14.1@99.5,86.75 100.138,87.388 ; U1.14@102.45,89.125 101.875,89.125 100.138,87.388
CAM_ENABLE: CN1.11 U5.20 U41.1 | length 57.9
  Top Layer w0.1: CN1.11@23.2,91.525 23.025,91.35 23.025,89.562 U41.1@22.975,89.512 22.988,89.5 v1(23.55,89.5) ; v1(64.555,80.075) U5.20@65.775,80.075
  Signal Layer 2 w0.1: v1(23.4,82.375) 25.2,82.375 26.6,83.775 55.849,83.775 55.899,83.725 64.675,83.725 v1(65.1,84.15)
  Bottom Layer w0.1: v1(23.4,82.375) 23.4,86.55 23.55,86.7 v1(23.55,89.5) ; v1(64.555,80.075) 64.555,83.605 v1(65.1,84.15)
CAM_RESET: CN1.12 U5.21 U40.1 | length 53.6
  Top Layer w0.1: CN1.12@24.2,91.525 24.2,90.125 24.325,90 24.325,89.55 U40.1@24.3,89.525 ; U40.1@24.325,89.538 v1(24.875,89.538) ; v1(54.9,87.55) 54.9,81.65 56.475,80.075 60.975,80.075 61.625,79.425 U5.21@65.775,79.425
  Signal Layer 2 w0.1: v1(26.025,86.15) 26.05,86.125 28.931,86.125 29.181,86.375 30.7,86.375 31.875,87.55 v1(54.9,87.55)
  Bottom Layer w0.1: v1(24.875,89.538) 24.875,87.3 v1(26.025,86.15)
CC1: R147.2 R149.1 U25.3 | length 2.4
  Top Layer w0.1: R149.1@19.17,17.089 R147.2@19.17,18.139 19.37,18.339 U25.3@20.42,18.339
CC2: R144.1 R145.2 U25.1 | length 2.4
  Top Layer w0.1: R144.1@19.17,20.625 19.17,19.55 19.37,19.35 U25.1@20.42,19.35
CLK_N: CN1.8 U2.E2 | length 28.8
  Top Layer w0.09: CN1.8@20.2,91.525 v1(20.2,92.8)
  Signal Layer 1 w0.075: v3(32.375,89.35) 32.346,89.379 32.346,89.514 32.09,89.77 32.09,91.45 32.356,91.717 32.356,92.731 v1(32.376,92.751)
  Bottom Layer w0.09: v1(20.2,92.8) 20.283,92.8 20.483,93 21.725,93 21.925,93.2 21.943,93.2 22.297,93.2 22.395,93.103 22.395,91.975 22.644,91.725 23.055,91.725 23.305,91.975 23.305,93.144 23.402,93.242 23.597,93.242 23.695,93.144 23.695,91.975 23.944,91.725 24.355,91.725 24.605,91.975 24.605,93.103 24.702,93.2 24.823,93.2 27.475,93.2 28.467,93.2 28.717,93.45 28.717,93.761 28.814,93.859 29.009,93.859 29.107,93.761 29.107,92.631 29.356,92.381 29.767,92.381 30.017,92.631 30.017,93.761 30.114,93.859 30.309,93.859 30.407,93.761 30.407,92.631 30.656,92.381 31.067,92.381 31.317,92.631 31.317,93.103 31.414,93.2 31.535,93.2 32.872,93.2 32.925,93.147 32.925,92.825 32.859,92.759 32.384,92.759 v1(32.376,92.751)
CLK_P: CN1.9 U2.D1 | length 27.9
  Top Layer w0.09: CN1.9@21.2,91.525 21.2,93.15 v1(21.475,93.425)
  Signal Layer 1 w0.075: v3(32.775,89.75) 32.746,89.779 32.611,89.779 32.465,89.925 32.465,91.295 32.731,91.561 32.731,92.131 v1(32.775,92.175)
  Bottom Layer w0.09: v1(21.475,93.425) 21.51,93.46 21.943,93.46 22.405,93.46 22.655,93.21 22.655,92.082 22.752,91.985 22.947,91.985 23.045,92.082 23.045,93.252 23.294,93.502 23.705,93.502 23.955,93.252 23.955,92.082 24.052,91.985 24.247,91.985 24.345,92.082 24.345,93.21 24.594,93.46 24.823,93.46 27.475,93.46 28.359,93.46 28.457,93.557 28.457,93.869 28.706,94.119 29.117,94.119 29.367,93.869 29.367,92.738 29.464,92.641 29.659,92.641 29.757,92.738 29.757,93.869 30.006,94.119 30.417,94.119 30.667,93.869 30.667,92.738 30.764,92.641 30.959,92.641 31.057,92.738 31.057,93.21 31.306,93.46 31.535,93.46 32.98,93.46 33.185,93.255 33.185,92.585 v1(32.775,92.175)
DATA1_N: CN1.2 U2.F1 | length 28.4
  Top Layer w0.09: CN1.2@14.2,91.525 14.2,92.15 14.455,92.405 14.517,92.405 14.57,92.458 14.57,93.405 v1(14.2,93.775) ; v1(31.75,95.875) 31.75,95.704 31.8,95.654 31.225,95.079 31.225,92.673 32.52,91.378 32.52,90.688 32.04,90.208 32.04,89.99 31.985,89.935 31.985,89.76 U2.F1@31.975,89.75
  Bottom Layer w0.09: v1(14.2,93.775) 14.57,94.145 14.57,94.563 15.642,95.635 17.467,95.635 31.485,95.635 31.725,95.875 v1(31.75,95.875)
DATA1_P: CN1.3 U2.E1 | length 27.8
  Top Layer w0.09: CN1.3@15.2,91.525 15.2,92.15 14.945,92.405 14.883,92.405 14.83,92.458 14.83,93.405 v1(15.2,93.775) ; v1(32.1,95.3) 31.814,95.3 31.485,94.971 31.485,92.781 32.78,91.486 32.78,90.58 32.3,90.1 32.3,90.02 32.375,89.945 U2.E1@32.375,89.75
  Bottom Layer w0.09: v1(15.2,93.775) 14.83,94.145 14.83,94.455 15.75,95.375 17.575,95.375 32.025,95.375 v1(32.1,95.3)
DATA2_N: CN1.5 U2.D2 | length 29.2
  Top Layer w0.09: CN1.5@17.2,91.525 17.377,91.702 17.377,92.532 17.595,92.75 17.595,93.63 v1(17.225,94) ; v1(32.825,95.15) 32.825,94.929 32.55,94.654 32.55,93.775 32.55,93.342 33.265,92.627 v3@33.265,91.2
  Signal Layer 1 w0.075: v3(32.775,89.35) 32.825,89.35 32.9,89.425 33.315,89.425 33.849,89.959 33.849,90.621 33.415,91.055 33.27,91.2 v3(33.26,91.2)
  Bottom Layer w0.09: v1(17.225,94) 17.595,94.37 17.595,94.558 17.872,94.835 21.845,94.835 22.724,94.835 22.974,94.585 22.974,94.367 23.071,94.27 23.266,94.27 23.364,94.367 23.364,94.609 23.613,94.859 24.024,94.859 24.274,94.609 24.274,94.367 24.371,94.27 24.566,94.27 24.664,94.367 24.664,94.609 24.913,94.859 25.324,94.859 25.574,94.609 25.574,94.367 25.671,94.27 25.866,94.27 25.964,94.367 25.964,94.609 26.213,94.859 26.624,94.859 26.874,94.609 26.874,94.367 26.971,94.27 27.166,94.27 27.264,94.367 27.264,94.585 27.513,94.835 28.557,94.835 32.51,94.835 v1(32.825,95.15)
DATA2_P: CN1.6 U2.C1 | length 27.8
  Top Layer w0.09: CN1.6@18.2,91.525 18.073,91.652 18.073,92.532 17.855,92.75 17.855,93.63 v1(18.225,94) ; v3(33.26,90.68) 33.535,90.955 33.535,91.314 33.525,91.324 33.525,92.735 32.81,93.45 32.81,94.546 32.889,94.625 33.225,94.625 v1(33.275,94.575)
  Signal Layer 1 w0.075: v3(33.175,89.75) 33.474,90.049 33.474,90.466 v3(33.26,90.68)
  Bottom Layer w0.09: v1(18.225,94) 17.855,94.37 17.855,94.45 17.98,94.575 21.845,94.575 22.616,94.575 22.714,94.478 22.714,94.26 22.963,94.01 23.374,94.01 23.624,94.26 23.624,94.502 23.721,94.599 23.916,94.599 24.014,94.502 24.014,94.26 24.263,94.01 24.674,94.01 24.924,94.26 24.924,94.502 25.021,94.599 25.216,94.599 25.314,94.502 25.314,94.26 25.563,94.01 25.974,94.01 26.224,94.26 26.224,94.502 26.321,94.599 26.516,94.599 26.614,94.502 26.614,94.26 26.863,94.01 27.274,94.01 27.524,94.26 27.524,94.478 27.621,94.575 28.557,94.575 v1(33.275,94.575)
DCMI_D0: TP32.1 U4.13 U14.A2 | length 100.5
  Top Layer w0.075: 67.475,43.125 67.475,42.388 68.475,41.388 U14.A2@68.475,40.65
  Top Layer w0.1: TP32.1@9.5,79.45 13.975,79.45 14.575,80.05 v1(17,80.05) U4.13@19.65,80.05 ; v1(66.775,69.225) 66.725,69.175 66.725,56.276 66.775,56.226 66.775,49.4 67.478,48.697 67.478,43.26 67.475,43.257 67.475,43.125
  Signal Layer 2 w0.219: v1(17,69.225) v1(66.775,69.225)
  Bottom Layer w0.1: v1(17,69.225) 16.975,69.25 16.975,72.631 16.825,72.781 16.825,79.766 17,79.941 v1(17,80.05)
DCMI_D1: U4.14 U14.B1 | length 87.7
  Top Layer w0.075: 66.55,43.125 66.65,43.025 66.65,41.05 67.55,40.15 U14.B1@67.975,40.15
  Top Layer w0.1: U4.14@19.65,79.65 v1(21,79.65) ; v1(65.525,69.725) 65.45,69.65 65.45,49.575 65.125,49.25 65.125,44.55 66.55,43.125
  Signal Layer 2 w0.219: v1(21,69.725) v1(65.525,69.725)
  Bottom Layer w0.1: v1(21,69.725) 20.6,70.125 20.6,75.85 20.125,76.325 20.125,78.775 v1(21,79.65)
DCMI_D2: U4.16 U14.G2 | length 86.8
  Top Layer w0.075: 65.175,38.917 66.647,37.445 67.769,37.445 67.811,37.404 68.079,37.404 68.314,37.639 68.464,37.639 U14.G2@68.475,37.65
  Top Layer w0.1: U4.16@19.65,78.85 v1(22.8,78.85) ; v1(56.675,72.925) 56.675,54.95 57.975,53.65 57.975,50.625 59.4,49.2 59.4,41.475 61.2,39.675 64.417,39.675 65.175,38.917
  Signal Layer 2 w0.219: v1(22.8,72.925) v1(56.675,72.925)
  Bottom Layer w0.1: v1(22.8,72.925) 23.1,73.225 23.1,76.619 22.6,77.119 22.6,78.566 22.8,78.766 v1(22.8,78.85)
DCMI_D3: U4.17 U14.H2 | length 88.4
  Top Layer w0.075: 65.175,38.325 66.393,37.107 67.629,37.107 67.671,37.066 68.353,37.066 68.438,37.15 U14.H2@68.475,37.15
  Top Layer w0.1: v1(18.475,78.45) U4.17@19.65,78.45 ; v1(55.8,74) 55.8,67.899 55.85,67.849 55.85,54.7 57.25,53.3 57.25,49.424 57.45,49.224 57.45,42.5 60.775,39.175 64.325,39.175 65.175,38.325
  Signal Layer 2 w0.219: v1(18.475,74) v1(55.8,74)
  Bottom Layer w0.1: v1(18.475,74) v1(18.475,78.45)
DCMI_D4: U4.19 U14.F3 | length 85.3
  Top Layer w0.075: 65.175,42.124 65.29,42.009 65.29,40.01 66.903,38.397 68.578,38.397 68.814,38.161 68.964,38.161 U14.F3@68.975,38.15
  Top Layer w0.1: U4.19@19.65,77.65 v1(21.975,77.65) ; v1(60.7,72.35) 60.65,72.3 60.65,52.7 62.3,51.05 62.3,44.992 65.092,42.2 65.099,42.2 65.175,42.124
  Signal Layer 2 w0.219: v1(21.975,72.35) v1(60.7,72.35)
  Bottom Layer w0.1: v1(21.975,72.35) 21.7,72.625 21.7,75.675 21.975,75.95 v1(21.975,77.65)
DCMI_D5: U4.20 U14.C2 | length 89.8
  Top Layer w0.075: 65.625,43.125 66.14,42.61 66.14,40.585 67.325,39.4 68.225,39.4 U14.C2@68.475,39.65
  Top Layer w0.1: v1(17.4,77.25) U4.20@19.65,77.25 ; v1(63.575,70.275) 64.4,69.45 64.4,64.125 63.575,63.3 63.575,61.001 63.5,60.926 63.5,54.125 64.325,53.3 64.325,44.425 65.625,43.125
  Signal Layer 2 w0.219: v1(17.4,70.275) v1(63.575,70.275)
  Bottom Layer w0.1: v1(17.4,70.275) v1(17.4,77.25)
DCMI_D6: U4.22 U14.D1 | length 87.4
  Top Layer w0.075: 65.325,43.125 65.97,42.48 65.97,40.43 67.25,39.15 U14.D1@67.975,39.15
  Top Layer w0.1: v1(17.95,76.45) U4.22@19.65,76.45 ; v1(63.2,71.3) 63.25,71.25 63.25,70.551 63.15,70.451 63.15,69.743 64.075,68.818 64.075,64.327 63.25,63.502 63.25,53 64.05,52.2 64.05,44.4 65.325,43.125
  Signal Layer 2 w0.219: v1(17.95,71.3) v1(63.2,71.3)
  Bottom Layer w0.1: v1(17.95,71.3) v1(17.95,76.45)
DCMI_D7: U4.23 U14.C3 | length 84.6
  Top Layer w0.075: 66.267,43.125 66.48,42.912 66.48,40.845 67.425,39.9 68.725,39.9 U14.C3@68.975,39.65
  Top Layer w0.1: U4.23@19.65,76.05 v1(21.4,76.05) ; v1(65.175,70.8) 65.175,70.678 65.025,70.528 65.025,69.624 65.175,69.474 65.175,49.583 64.925,49.333 64.925,44.467 66.267,43.125
  Signal Layer 2 w0.219: v1(21.4,70.8) v1(65.175,70.8)
  Bottom Layer w0.1: v1(21.4,70.8) v1(21.4,76.05)
DCMI_HSYNC: TP21.1 U4.5 U14.E3 | length 102.2
  Top Layer w0.075: 65.175,42.7 65.63,42.245 65.63,40.22 67.115,38.735 68.15,38.735 68.315,38.9 68.725,38.9 U14.E3@68.975,38.65
  Top Layer w0.1: TP21.1@12,83.95 12.7,83.25 v1(16.5,83.25) 17.35,83.25 17.5,83.4 18.1,83.4 18.275,83.225 19.625,83.225 U4.5@19.65,83.25 ; v1(61.9,71.825) 61.95,71.775 61.95,53.875 62.375,53.45 62.375,52.675 63.575,51.475 63.575,44.3 65.175,42.7
  Signal Layer 2 w0.219: v1(16.5,71.825) v1(61.9,71.825)
  Bottom Layer w0.1: v1(16.5,71.825) v1(16.5,83.25)
DCMI_PIXCLK: TP13.1 U4.2 U14.C6 | length 109.4
  Top Layer w0.075: 69.9,43.125 69.9,43.044 70.059,42.884 70.059,40.414 70.221,40.252 70.221,40.229 70.225,40.225 70.225,39.9 U14.C6@70.475,39.65
  Top Layer w0.1: TP13.1@12,86.95 14,86.95 v1(15.925,85.025) 16.5,84.45 U4.2@19.65,84.45 ; v1(69.475,69.125) 69.075,68.725 69.075,60.347 69.503,59.919 69.503,59.527 69.475,59.499 69.475,48.15 69.1,47.775 69.1,45.675 69.425,45.35 69.425,43.75 69.9,43.275 69.9,43.125
  Signal Layer 2 w0.219: v1(15.925,68.6) 66.868,68.6 67.393,69.125 v1(69.475,69.125)
  Bottom Layer w0.1: v1(15.925,68.6) v1(15.925,85.025)
DCMI_VSYNC: TP17.1 U4.3 U14.F2 | length 107.4
  Top Layer w0.075: 65.175,39.483 65.579,39.079 65.579,39.071 66.75,37.9 68.225,37.9 U14.F2@68.475,38.15
  Top Layer w0.1: TP17.1@9.5,85.45 14,85.45 v1(15.4,84.05) 17.9,84.05 18.05,84.2 18.75,84.2 18.9,84.05 U4.3@19.65,84.05 ; v1(60.325,73.475) 60.35,73.45 60.35,72.601 60.275,72.526 60.275,72.174 60.35,72.099 60.35,52.425 61.95,50.825 61.95,45 62.875,44.075 62.875,41.802 62.83,41.757 62.83,40.414 62.919,40.325 64.333,40.325 65.175,39.483
  Signal Layer 2 w0.219: v1(15.4,73.475) v1(60.325,73.475)
  Bottom Layer w0.1: v1(15.4,73.475) 15.4,73.597 15.5,73.697 15.5,83.766 15.486,83.78 15.486,83.964 v1(15.4,84.05)
DDR_A0: U14.H20 U17.N3 | length 30.1
  Top Layer w0.075: U14.H20@77.47,37.145 77.643,37.145 77.719,37.069 77.729,37.069 77.733,37.066 78.217,37.066 78.22,37.069 78.315,37.163 79.129,37.163 79.233,37.06 v2@79.59,37.06
  Top Layer w0.09: U17.N3@87.945,35.695 v2(88.35,36.1)
  Bottom Layer w0.09: v2@79.662,37 80.032,37.37 80.558,37.37 80.83,37.642 80.83,38.1 80.938,38.208 80.938,38.633 80.69,38.88 80.69,39.26 80.95,39.52 80.95,39.788 80.675,40.063 80.675,40.25 80.938,40.513 80.938,41.637 80.6,41.975 80.6,42.15 81.25,42.8 86.405,42.8 86.702,42.502 86.702,42.252 86.415,41.965 86.415,41.56 86.725,41.25 86.725,41.02 86.465,40.76 85.732,40.76 85.087,40.115 84.595,40.115 82.93,38.45 82.93,37.098 84.148,35.88 84.916,35.88 85.257,35.54 87.79,35.54 v2(88.35,36.1)
  other v2: 79.675,37.025
DDR_A1: U14.N21 U17.P7 | length 29.9
  Top Layer w0.075: U14.N21@77.975,34.65 78.013,34.65 78.093,34.73 78.892,34.73 79.467,34.155 v2@80.755,34.155
  Top Layer w0.09: v2(86.75,32.025) 87.15,32.425 U17.P7@87.15,32.5
  Bottom Layer w0.09: v2(80.7,34.175) 80.7,34.173 81.285,33.588 81.285,33.1 81.535,32.85 81.535,26.379 81.657,26.257 81.738,26.257 82.057,25.938 82.057,25.857 82.195,25.719 84.828,25.719 85.009,25.9 85.175,25.9 85.356,25.719 85.593,25.719 85.725,25.851 85.725,25.975 85.454,26.246 85.454,26.346 85.784,26.675 85.925,26.675 86.075,26.525 86.275,26.525 86.35,26.6 86.35,27.2 86.275,27.275 85.75,27.275 85.62,27.405 85.62,27.595 85.7,27.675 86.15,27.675 86.219,27.744 86.219,27.919 86.117,28.02 85.377,28.02 84.698,28.698 84.598,28.698 84.525,28.625 84.525,28.545 84.425,28.445 84.295,28.445 84.19,28.55 84.19,31.395 84.3,31.505 84.3,31.6 84.19,31.71 84.19,31.85 84.425,32.085 84.7,32.085 84.85,31.935 85.21,31.935 85.36,32.085 85.565,32.085 85.625,32.025 85.625,31.81 85.695,31.74 86.21,31.74 86.26,31.79 86.26,31.95 86.335,32.025 v2(86.75,32.025)
DDR_A2: U14.G20 U17.P3 | length 30.3
  Top Layer w0.075: U14.G20@77.47,37.645 77.48,37.635 77.634,37.635 77.861,37.407 77.869,37.407 77.873,37.404 78.077,37.404 78.176,37.503 79.366,37.503 79.535,37.672 79.722,37.672 v2(79.775,37.725)
  Top Layer w0.09: U17.P3@87.145,35.695 v2(87.55,36.1)
  Bottom Layer w0.09: v2(79.775,37.725) 79.875,37.625 80.388,37.625 80.595,37.832 80.595,38.565 80.25,38.91 80.25,39.23 80.575,39.555 80.575,39.67 80.195,40.05 80.195,40.245 80.5,40.55 80.5,40.7 80.195,41.005 80.195,41.12 80.475,41.4 80.475,41.62 80.195,41.9 80.195,42.185 81.13,43.12 86.495,43.12 87.15,42.465 87.15,42.29 86.705,41.845 86.705,41.68 86.81,41.575 87.125,41.575 87.26,41.44 87.26,41.145 86.585,40.47 85.852,40.47 85.207,39.825 84.715,39.825 83.22,38.33 83.22,37.19 84.24,36.17 85.036,36.17 85.377,35.83 87.347,35.83 87.4,35.882 87.4,35.892 87.55,36.042 v2(87.55,36.1)
DDR_A3: U14.H19 U17.N2 | length 30.8
  Top Layer w0.075: U14.H19@76.97,37.145 77.224,37.399 77.629,37.399 77.79,37.238 77.799,37.238 77.803,37.235 78.147,37.235 78.245,37.333 79.45,37.333 79.497,37.38 80.105,37.38 80.25,37.525 v2(80.25,37.975)
  Top Layer w0.09: U17.N2@87.945,36.495 v2(88.35,36.9)
  Bottom Layer w0.09: v2(80.25,37.975) 80.25,38.5 79.905,38.845 79.905,42.305 81.01,43.41 86.615,43.41 87.55,42.475 87.55,41.025 86.705,40.18 85.972,40.18 85.327,39.535 84.835,39.535 83.51,38.21 83.51,37.282 84.332,36.46 85.156,36.46 85.492,36.125 87.025,36.125 87.4,36.5 87.95,36.5 v2(88.35,36.9)
DDR_A4: U14.R19 U17.P8 | length 30.6
  Top Layer w0.09: U17.P8@87.15,31.7 87.489,31.361 87.489,30.72 87.6,30.609 v2(87.6,30.525)
  Top Layer w0.1: v2(76.55,33.675) 76.563,33.663 76.962,33.663 U14.R19@76.975,33.65
  Bottom Layer w0.09: v2(76.55,33.675) 76.558,33.683 77.567,33.683 77.8,33.45 77.8,31.1 78.425,30.475 78.425,26.192 81.219,23.398 88.448,23.398 90,24.95 90,27.629 88.45,29.179 88.45,29.662 87.98,30.132 87.98,30.195 87.65,30.525 v2(87.6,30.525)
DDR_A5: U14.F20 U17.P2 | length 30.1
  Top Layer w0.075: U14.F20@77.47,38.145 77.479,38.136 77.635,38.136 77.871,37.9 78.31,37.9 78.33,37.88 78.768,37.88 78.974,38.086 78.974,38.174 79.123,38.323 79.618,38.323 79.716,38.225 v2(79.8,38.225)
  Top Layer w0.09: U17.P2@87.145,36.495 v2(87.55,36.9)
  Bottom Layer w0.09: v2(79.8,38.225) 79.8,38.515 79.615,38.7 79.615,43.19 80.125,43.7 87.3,43.7 87.905,43.095 87.905,40.13 87.665,39.89 86.092,39.89 85.447,39.245 84.962,39.245 83.8,38.083 83.8,37.373 84.423,36.75 85.277,36.75 85.641,36.386 86.316,36.386 86.41,36.48 86.818,36.48 87.238,36.9 v2(87.55,36.9)
DDR_A6: U14.R21 U17.R8 | length 29.8
  Top Layer w0.09: U14.R21@77.974,33.65 78.5,33.65 v2(78.5,33.625) ; U17.R8@86.35,31.7 86.675,31.375 86.675,31.178 86.775,31.078 86.775,30.801 86.875,30.701 v2(86.875,30.45)
  Bottom Layer w0.09: v2(78.5,33.625) 78.208,33.625 78.09,33.507 78.09,31.22 78.715,30.595 78.715,26.312 81.339,23.688 88.328,23.688 89.66,25.02 89.66,25.465 89.25,25.875 89.25,26.665 89.66,27.075 89.66,27.559 88.16,29.059 88.16,29.39 87.95,29.6 87.447,29.6 87.28,29.767 87.28,29.967 86.85,30.397 86.875,30.422 v2(86.875,30.45)
DDR_A7: U14.J17 U17.R2 | length 31.4
  Top Layer w0.09: v2@75.47,36.645 U14.J17@75.97,36.645 ; v2@75.525,36.65 v2(75.55,36.65) U14.J17@75.975,36.65 ; v2(85.95,36.975) 86.35,36.575 U17.R2@86.35,36.5
  Bottom Layer w0.09: v2(75.55,36.65) 75.774,36.875 76.187,36.875 76.382,37.07 76.929,37.07 77.61,37.751 77.61,38.11 78.4,38.9 78.4,40.287 79.035,40.922 79.035,43.43 79.885,44.28 87.895,44.28 88.485,43.69 88.485,39.635 88.16,39.31 86.333,39.31 85.688,38.665 85.202,38.665 84.38,37.843 84.38,37.557 84.607,37.33 85.595,37.33 v2(85.95,36.975)
DDR_A8: U14.P19 U17.T8 | length 31
  Top Layer w0.075: U14.P19@76.975,34.15 77.225,33.9 77.225,33.5 77.325,33.4 78.175,33.4 78.295,33.28 78.667,33.28 78.682,33.295 78.968,33.295 79.17,33.093 79.17,32.655 v2(79.225,32.6)
  Top Layer w0.09: U17.T8@85.55,31.7 85.975,31.275 85.975,30.55 v2(86.075,30.45)
  Bottom Layer w0.09: v2(79.225,32.6) 78.55,32.6 78.38,32.43 78.38,31.34 79.005,30.715 79.005,26.432 81.459,23.979 83.35,23.979 ; 83.35,23.978 87.225,23.978 ; v2(86.075,30.45) 86.075,30.4 86.05,30.375 86.26,30.165 86.472,30.165 87.437,29.2 87.609,29.2 88.525,28.284 88.525,28.15 89.125,27.55 89.125,27.25 88.25,26.375 88.25,25.95 88.8,25.4 88.8,24.675 88.103,23.978 87.246,23.978
DDR_A9: U14.G21 U17.R3 | length 29.5
  Top Layer w0.075: U14.G21@77.975,37.65 77.998,37.673 79.023,37.673 v2(79.325,37.975)
  Top Layer w0.09: U17.R3@86.345,35.695 86.75,36.1 v2(86.75,36.9)
  Bottom Layer w0.09: v2(79.325,37.975) 79.325,43.31 80.005,43.99 87.46,43.99 88.195,43.255 88.195,40.01 87.785,39.6 86.212,39.6 85.567,38.955 85.082,38.955 84.09,37.963 84.09,37.465 84.515,37.04 85.397,37.04 85.807,36.63 86.15,36.63 86.42,36.9 v2(86.75,36.9)
DDR_A10: U14.L18 U17.L7 | length 31.5
  Top Layer w0.09: v2(89.145,32.095) U17.L7@89.545,32.495
  Top Layer w0.1: U14.L18@76.475,35.65 76.475,35.356 76.55,35.281 v2(76.55,35.2)
  Bottom Layer w0.09: v2(76.55,35.2) 76.775,34.975 77.725,34.975 78.435,34.265 78.885,34.265 78.995,34.155 80.218,34.155 80.678,33.695 80.768,33.695 80.995,33.468 80.995,32.98 81.245,32.73 81.245,31.52 81.098,31.373 81.098,31.277 81.245,31.13 81.245,30.62 81.035,30.41 81.035,30.335 81.245,30.125 81.245,28.825 81.15,28.73 81.15,28.575 81.245,28.48 81.245,26.259 82.075,25.429 85.713,25.429 86.105,25.82 86.105,26.005 86.208,26.108 86.392,26.108 86.64,26.355 86.64,27.907 86.237,28.31 85.497,28.31 84.48,29.327 84.48,31.143 84.982,31.645 85.38,31.645 85.575,31.45 88,31.45 88.287,31.737 88.787,31.737 v2(89.145,32.095)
